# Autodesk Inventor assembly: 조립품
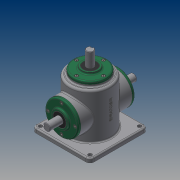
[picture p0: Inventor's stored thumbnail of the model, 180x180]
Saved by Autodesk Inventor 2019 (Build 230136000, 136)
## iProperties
Created: 2019-03
Part Number: 조립품
Material: 일반
Document SubType Name: Assembly
Designer: PC312-18
Author: PC312-18
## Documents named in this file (16)
- C:\Users\PC312-18\Desktop\490314V1006\조립품.iam
- C:\Users\PC312-18\Desktop\490314V1006\본체.ipt
- C:\Users\PC312-18\Desktop\490314V1006\커버.ipt
- C:\Users\PC312-18\Desktop\490314V1006\베어링 6203.ipt
- C:\Users\PC312-18\Desktop\490314V1006\오일 실.ipt
- 오일 실.ipt
- C:\Users\PC312-18\Desktop\490314V1006\메인 축.ipt
- 메인 축.ipt
- C:\Users\PC312-18\Desktop\490314V1006\키 5x5.ipt
- C:\Users\PC312-18\Desktop\490314V1006\메인 베벨기어.ipt
- C:\Users\PC312-18\Desktop\490314V1006\서브 축.ipt
- 서브 축.ipt
- C:\Users\PC312-18\Desktop\490314V1006\키 4x4.ipt
- C:\Users\PC312-18\Desktop\490314V1006\서브 베벨기어.ipt
- C:\Users\PC312-18\Desktop\490314V1006\볼트 M4.ipt
- 볼트 M4.ipt
